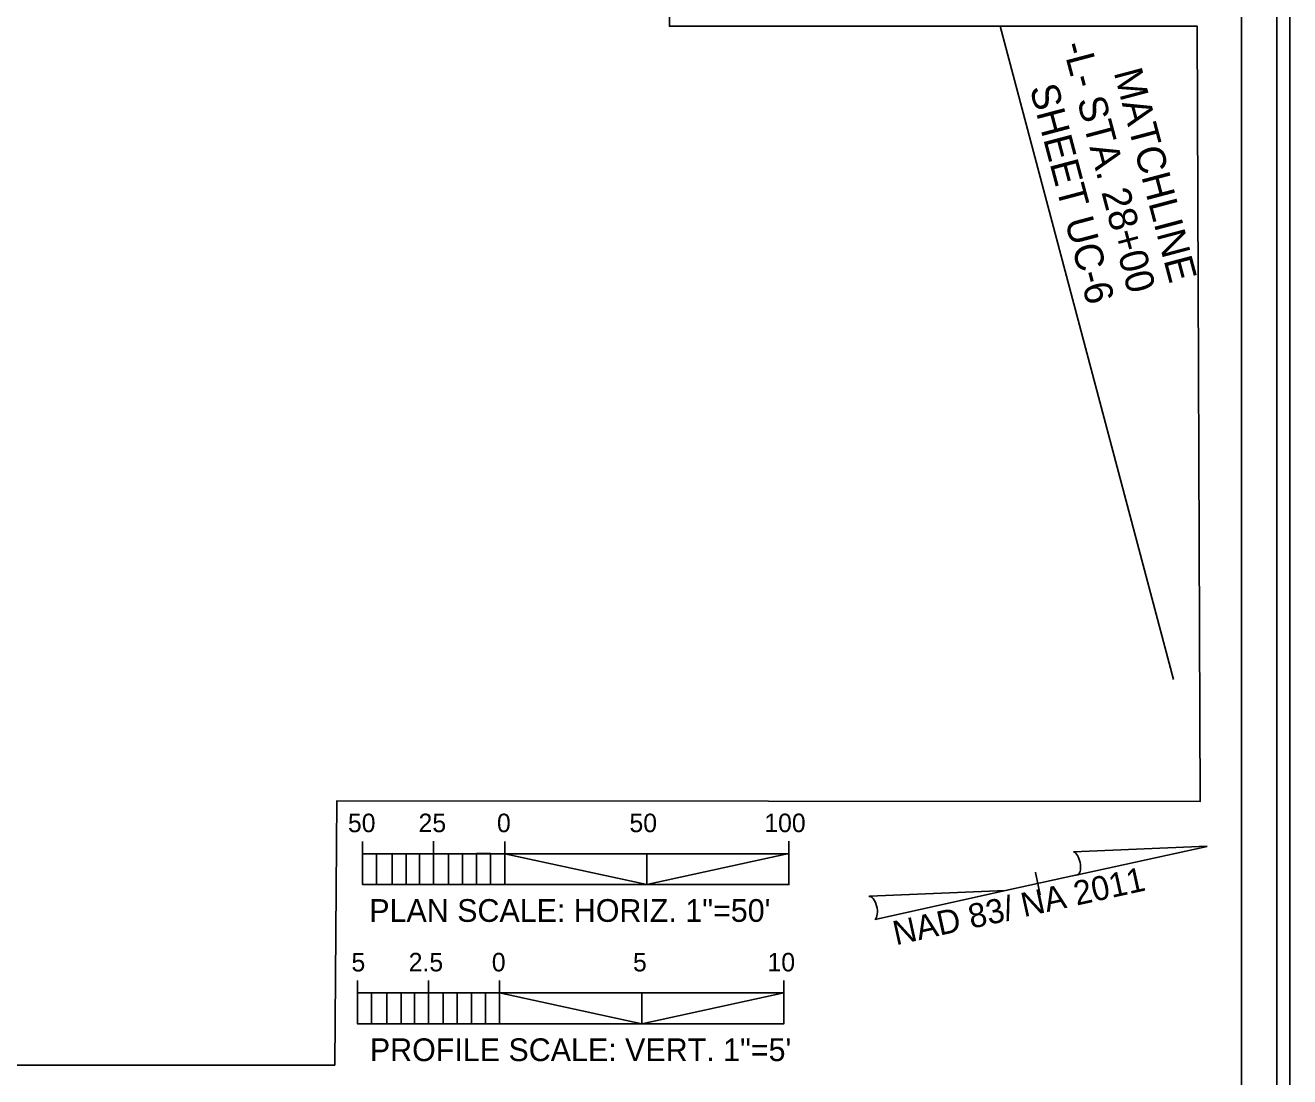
# Model space of a CAD drawing. Extents: x 0 to 2694, y -1 to 1501.
# Drawn here: x 2.092 to 2.833, y 0.886 to 1.503 of the extents above; entities that cross this region are included whole.
import ezdxf

# ---------------------------------------------------------------- set-up
doc = ezdxf.new("R2010")
doc.units = 0
for name, color, linetype in [('3pt Criteria MH CELL', 7, 'Continuous'), ('Aband Utility MH (M1) CELL', 7, 'Continuous'), ('Air Release (M1) CELL', 7, 'Continuous'), ('COGO Default Point Elevation', 7, 'Continuous')]:
    doc.layers.add(name, color=color, linetype=linetype)

msp = doc.modelspace()

# ---------------------------------------------------------------- linework, layer by layer
at = {"layer": '3pt Criteria MH CELL'}
for p, q in [((2.28979, 0.99871), (2.28979, 1.02404)), ((2.33146, 1.01681), (2.33146, 1.02408)), ((2.37312, 1.01681), (2.37312, 1.02405)), ((2.53979, 1.01683), (2.53979, 1.02408)), ((2.53979, 1.0168), (2.28979, 1.01681)), ((2.34837, 1.01683), (2.34837, 0.99872)), ((2.45646, 1.01683), (2.45646, 0.99872)), ((2.53979, 0.9987), (2.53979, 1.01683)), ((2.28979, 0.9987), (2.53979, 0.99871)), ((2.28677, 0.91707), (2.28677, 0.94239)), ((2.32844, 0.93516), (2.32844, 0.94243)), ((2.37011, 0.93516), (2.3701, 0.94241)), ((2.53677, 0.93518), (2.53677, 0.94243)), ((2.53677, 0.93515), (2.28677, 0.93517)), ((2.34535, 0.93518), (2.34535, 0.91707)), ((2.45344, 0.93518), (2.45344, 0.91707)), ((2.53677, 0.91705), (2.53677, 0.93518)), ((2.28677, 0.91705), (2.53677, 0.91706))]:
    msp.add_line(p, q, dxfattribs=at)
for points in [[(2.28979, 1.01681), (2.29804, 1.01681), (2.29804, 0.9987), (2.28979, 0.9987)], [(2.30711, 1.01683), (2.31536, 1.01681), (2.31536, 0.9987), (2.30713, 0.9987)], [(2.32321, 1.01681), (2.33146, 1.01681), (2.33146, 0.99872), (2.32321, 0.99872)], [(2.34012, 1.01681), (2.34837, 1.01683), (2.34837, 0.99872), (2.34012, 0.99872)], [(2.35662, 1.01683), (2.36487, 1.01683), (2.36487, 0.9987), (2.35662, 0.99872)], [(2.37312, 1.01681), (2.45646, 0.99872), (2.37313, 0.9987)], [(2.53979, 1.01683), (2.45646, 0.99872), (2.53979, 0.9987)], [(2.28677, 0.93517), (2.29502, 0.93517), (2.29502, 0.91705), (2.28677, 0.91705)], [(2.30409, 0.93518), (2.31234, 0.93516), (2.31234, 0.91705), (2.30411, 0.91705)], [(2.32019, 0.93516), (2.32844, 0.93516), (2.32844, 0.91707), (2.32019, 0.91707)], [(2.3371, 0.93516), (2.34535, 0.93518), (2.34535, 0.91707), (2.3371, 0.91707)], [(2.3536, 0.93518), (2.36185, 0.93518), (2.36185, 0.91705), (2.3536, 0.91707)], [(2.37011, 0.93516), (2.45344, 0.91707), (2.37011, 0.91705)], [(2.53677, 0.93518), (2.45344, 0.91707), (2.53677, 0.91705)]]:
    msp.add_lwpolyline(points, close=True, dxfattribs=at)
at = {"layer": 'Aband Utility MH (M1) CELL'}
for p, q in [((2.70657, 1.01797), (2.78495, 1.02119)), ((2.78497, 1.02111), (2.70716, 1.00402)), ((2.78497, 1.02111), (2.78499, 1.02103)), ((2.78497, 1.02111), (2.78499, 1.02103)), ((2.66679, 0.99516), (2.70944, 1.00452)), ((2.68424, 1.00581), (2.68422, 1.0059)), ((2.68551, 1.00004), (2.68424, 1.00581)), ((2.68426, 1.00573), (2.68712, 0.99271)), ((2.70716, 1.00402), (2.70936, 1.0045)), ((2.66679, 0.99516), (2.58689, 0.99186)), ((2.59021, 0.97826), (2.66679, 0.99516))]:
    msp.add_line(p, q, dxfattribs=at)
for centre, start_param, end_param in [((2.70724, 1.01106), 0.216388, 2.908219), ((2.58813, 0.9849), 0.201328, 3.141593)]:
    msp.add_ellipse(centre, major_axis=(0.00146, -0.0069), ratio=0.461098, start_param=start_param, end_param=end_param, dxfattribs=at)
at = {"layer": 'Air Release (M1) CELL'}
msp.add_lwpolyline([(0.30746, 0.89289), (0.30758, 1.69779), (0.7284, 1.69769), (0.7284, 1.75822), (2.46973, 1.75822), (2.46973, 1.50207), (2.7791, 1.50207), (2.78092, 1.04749), (2.27463, 1.04778), (2.27347, 0.89289)], close=True, dxfattribs=at)
at = {"layer": 'COGO Default Point Elevation'}
msp.add_line((2.76522, 1.11895), (2.66358, 1.50207), dxfattribs=at)
for points in [[(0.02749, 0.00833), (2.83333, 0.00833), (2.83333, 1.83333), (0.02749, 1.83333)], [(0.04916, 0.04166), (2.82583, 0.04166), (2.82583, 1.8), (0.04916, 1.8)], [(2.80499, 1.79583), (0.30499, 1.79583), (0.30499, 0.04583), (2.80499, 0.04583)]]:
    msp.add_lwpolyline(points, close=True, dxfattribs=at)

# ---------------------------------------------------------------- texts
at = {"layer": '3pt Criteria MH CELL'}
for s, height, p in [('50', 0.010867, (2.28123, 1.02942)), ('25', 0.010867, (2.32263, 1.02944)), ('0', 0.01087, (2.36859, 1.02942)), ('50', 0.010867, (2.44626, 1.02942)), ('100', 0.010867, (2.52531, 1.02944)), ('PLAN SCALE: HORIZ. 1"=50\'', 0.0133333, (2.29374, 0.97683)), ('5', 0.01087, (2.2833, 0.94777)), ('2.5', 0.010867, (2.31685, 0.94779)), ('0', 0.01087, (2.36557, 0.94777)), ('5', 0.01087, (2.44833, 0.94777)), ('10', 0.010867, (2.52719, 0.94779)), ('PROFILE SCALE: VERT. 1"=5\'', 0.0133333, (2.29409, 0.89518))]:
    msp.add_text(s, height=height, rotation=0.00136, dxfattribs=at).set_placement(p)
at = {"layer": 'Aband Utility MH (M1) CELL'}
msp.add_text('NAD 83/ NA 2011', height=0.0141667, rotation=12.38484, dxfattribs=at).set_placement((2.60245, 0.96308))
at = {"layer": 'COGO Default Point Elevation'}
for s, height, p in [('-L- STA. 28+00', 0.0166667, (2.69997, 1.49103)), ('MATCHLINE ', 0.016667, (2.73008, 1.47502)), ('SHEET UC-6', 0.016667, (2.68079, 1.46585))]:
    msp.add_text(s, height=height, rotation=284.85716, dxfattribs=at).set_placement(p)

doc.saveas('drawing.dxf')
